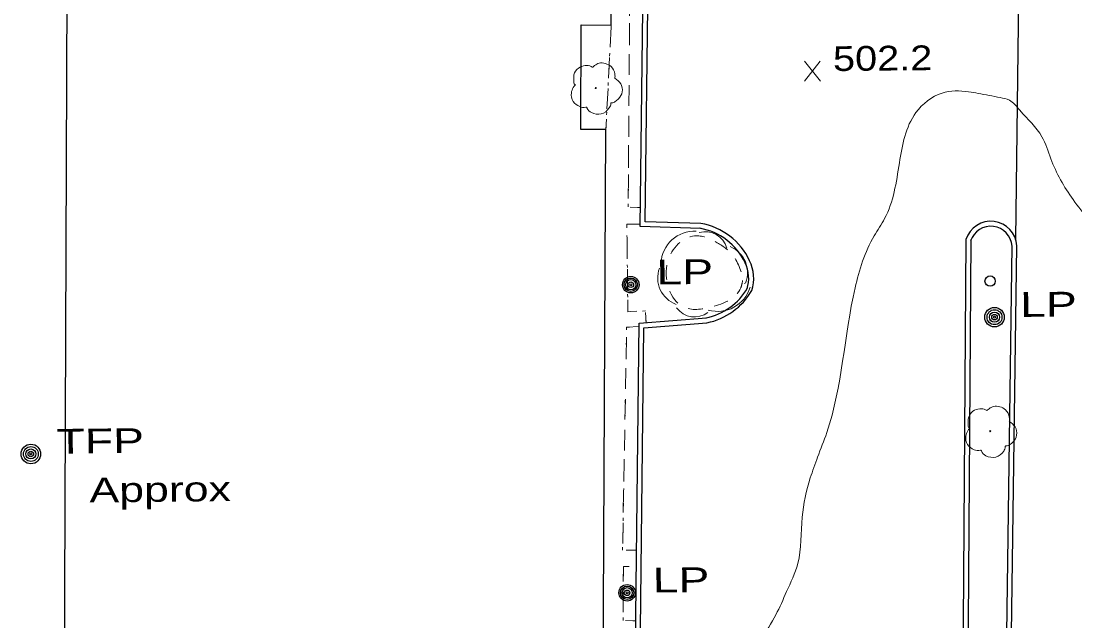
# Model space of a CAD drawing. Extents: x 2362213 to 2366494, y 6968794 to 6978110.
# Drawn here: x 2364038.5 to 2364243, y 6974850.3 to 6974966.6 of the extents above; entities that cross this region are included whole.
import ezdxf

# ---------------------------------------------------------------- set-up
doc = ezdxf.new("R2010")
doc.units = 0
doc.header["$LTSCALE"] = 1.9
doc.linetypes.add('DOTTED', pattern=[1.5, 0.3, -1.2])
doc.linetypes.add('SHORT_DASHED', pattern=[2.7, 1.5, -1.2])
for name, color, linetype, lineweight in [('11', 7, 'Continuous', 25), ('13', 7, 'Continuous', 13), ('2', 7, 'Continuous', 25), ('20', 7, 'Continuous', 25), ('29', 7, 'Continuous', 13), ('31', 7, 'Continuous', 25), ('35', 7, 'Continuous', 13)]:
    doc.layers.add(name, color=color, linetype=linetype, lineweight=lineweight)

msp = doc.modelspace()

# ---------------------------------------------------------------- linework, layer by layer
at = {"layer": '11'}
msp.add_lwpolyline([(2364144.499, 6974705.543), (2364144.65, 6974735.807), (2364151.03, 6974735.778), (2364151.301, 6974795.572), (2364145.771, 6974795.6), (2364145.92, 6974826.173), (2364151.409, 6974826.146), (2364152.012, 6974945.557), (2364147.142, 6974945.58), (2364147.239, 6974965.852), (2364153.059, 6974965.828), (2364153.569, 6975085.578), (2364148.939, 6975085.594), (2364149.041, 6975115.776), (2364154.952, 6975115.753), (2364155.191, 6975175.679), (2364150.001, 6975175.699), (2364150.119, 6975205.342), (2364048.33, 6975205.742), (2364046.369, 6974705.929)], close=True, dxfattribs=at)
at = {"layer": '13', "linetype": 'DOTTED'}
msp.add_line((2364152.012, 6974945.557), (2364153.029, 6974965.827), dxfattribs=at)
at = {"layer": '13'}
for p, q in [((2364152.82, 6974961.545), (2364153.012, 6974965.537)), ((2364156.564, 6974962.181), (2364156.596, 6974966.181)), ((2364152.517, 6974955.552), (2364152.719, 6974959.544)), ((2364156.521, 6974956.18), (2364156.553, 6974960.181)), ((2364152.214, 6974949.559), (2364152.416, 6974953.55)), ((2364156.479, 6974950.18), (2364156.51, 6974954.179)), ((2364152.012, 6974945.557), (2364152.113, 6974947.558)), ((2364156.436, 6974944.179), (2364156.468, 6974948.179)), ((2364156.393, 6974938.178), (2364156.425, 6974942.179)), ((2364156.35, 6974932.177), (2364156.382, 6974936.178)), ((2364158.727, 6974930.449), (2364156.726, 6974930.55)), ((2364156.161, 6974920.515), (2364156.113, 6974924.515)), ((2364156.228, 6974914.516), (2364156.18, 6974918.515)), ((2364159.789, 6974908.118), (2364159.72, 6974910.119)), ((2364156.108, 6974907.233), (2364158.426, 6974907.385)), ((2364155.924, 6974901.312), (2364155.996, 6974905.313)), ((2364155.811, 6974895.311), (2364155.883, 6974899.312)), ((2364155.708, 6974889.309), (2364155.78, 6974893.31)), ((2364155.595, 6974883.307), (2364155.667, 6974887.308)), ((2364155.492, 6974877.307), (2364155.564, 6974881.308)), ((2364155.38, 6974871.306), (2364155.451, 6974875.306)), ((2364155.277, 6974865.303), (2364155.349, 6974869.305)), ((2364157.939, 6974863.989), (2364155.939, 6974863.99)), ((2364155.354, 6974851.944), (2364155.376, 6974855.945)), ((2364157.79, 6974850.298), (2364155.789, 6974850.368))]:
    msp.add_line(p, q, dxfattribs=at)
at = {"layer": '13', "linetype": 'DOTTED'}
for points in [[(2364158.727, 6974930.449), (2364156.335, 6974930.566), (2364156.758, 6974987.024), (2364159.397, 6974987.069)], [(2364159.789, 6974908.118), (2364159.708, 6974910.399), (2364156.269, 6974910.236), (2364156.077, 6974927.215), (2364158.687, 6974927.22)], [(2364157.939, 6974863.989), (2364155.249, 6974863.993), (2364156.028, 6974907.232), (2364158.426, 6974907.385)], [(2364157.79, 6974850.298), (2364155.349, 6974850.384), (2364155.409, 6974860.824), (2364157.9, 6974860.778)]]:
    msp.add_lwpolyline(points, dxfattribs=at)
at = {"layer": '13'}
for points in [[(2364156.084, 6974926.515), (2364156.077, 6974927.215), (2364158.687, 6974927.22)], [(2364157.988, 6974910.322), (2364156.269, 6974910.236), (2364156.247, 6974912.516)], [(2364155.387, 6974857.945), (2364155.409, 6974860.824), (2364156.53, 6974860.805)]]:
    msp.add_lwpolyline(points, dxfattribs=at)
at = {"layer": '2'}
msp.add_line((2364231.509, 6974924.323), (2364232.2, 6974978.832), dxfattribs=at)
for points in [[(2364170.386, 6974926.411), (2364158.682, 6974926.739), (2364159.801, 6975021.385), (2364161.9, 6975204.204), (2364150.098, 6975204.381)], [(2364170.416, 6974927.371), (2364159.653, 6974927.669), (2364160.761, 6975021.375), (2364162.871, 6975205.153), (2364150.109, 6975205.341)], [(2364221.858, 6974924.261), (2364221.316, 6974849.932), (2364219.62, 6974747.611)], [(2364222.818, 6974924.25), (2364222.276, 6974849.922), (2364220.581, 6974747.59)], [(2364228.65, 6974747.647), (2364229.767, 6974847.793), (2364230.8, 6974923.046)], [(2364229.611, 6974747.636), (2364230.727, 6974847.782), (2364231.761, 6974923.035)], [(2364156.663, 6974749.151), (2364158.43, 6974908.005), (2364171.521, 6974909.05)], [(2364157.623, 6974749.14), (2364159.379, 6974907.114), (2364171.6, 6974908.091)]]:
    msp.add_lwpolyline(points, dxfattribs=at)
for centre, radius, start, end in [((2364168.111, 6974914.536), 12.08, 25.45495, 79.81805), ((2364168.111, 6974914.536), 13.04, 25.45495, 79.81805), ((2364226.693, 6974922.705), 5.079, 3.72178, 162.16418), ((2364226.693, 6974922.705), 4.119, 3.72178, 162.16418), ((2364172.998, 6974916.734), 7.684, 342.11796, 26.31952), ((2364172.998, 6974916.734), 6.724, 342.11796, 26.31952), ((2364169.016, 6974920.852), 12.06, 281.44766, 330.16517), ((2364169.016, 6974920.852), 13.02, 281.44766, 330.16517)]:
    msp.add_arc(centre, radius, start, end, dxfattribs=at)
at = {"layer": '20'}
for centre, radius in [((2364156.839, 6974915.481), 1.6), ((2364156.839, 6974915.481), 1.3), ((2364156.839, 6974915.481), 1), ((2364156.839, 6974915.481), 0.539), ((2364226.556, 6974916.185), 1), ((2364156.839, 6974915.481), 0.192), ((2364227.402, 6974909.183), 1.9), ((2364227.402, 6974909.183), 1.442), ((2364227.402, 6974909.183), 0.973), ((2364227.402, 6974909.183), 0.539), ((2364227.402, 6974909.183), 0.192), ((2364040.446, 6974882.651), 1.9), ((2364040.446, 6974882.651), 1.442), ((2364040.446, 6974882.651), 0.973), ((2364040.446, 6974882.651), 0.539), ((2364040.446, 6974882.651), 0.192), ((2364156.118, 6974855.732), 1.6), ((2364156.118, 6974855.732), 1.3), ((2364156.118, 6974855.732), 1), ((2364156.118, 6974855.732), 0.539), ((2364156.118, 6974855.732), 0.192)]:
    msp.add_circle(centre, radius, dxfattribs=at)
at = {"layer": '29'}
for centre in [(2364150.036, 6974953.628), (2364226.563, 6974887.074)]:
    msp.add_circle(centre, 0.1, dxfattribs=at)
for centre, radius, start, end in [((2364169.223, 6974919.358), 6.525, 87.4639, 177.4639), ((2364171.285, 6974921.427), 4.347, 15.47608, 105.47608), ((2364174.064, 6974917.827), 5.44, 338.17694, 68.17694), ((2364167.506, 6974916.768), 5.44, 159.6241, 249.6241), ((2364173.718, 6974916.83), 6.525, 253.61946, 343.61946), ((2364169.217, 6974913.573), 4.347, 216.6818, 306.6818)]:
    msp.add_arc(centre, radius, start, end, dxfattribs=at)
for points in [[(2364146.07, 6974954.2), (2364146.09, 6974954.21), (2364146.009, 6974954.279), (2364145.773, 6974954.908), (2364145.811, 6974956.188), (2364146.699, 6974957.487), (2364148.004, 6974957.969), (2364149.126, 6974957.78), (2364149.357, 6974957.652), (2364149.427, 6974957.653), (2364149.477, 6974957.693), (2364149.824, 6974957.987), (2364150.69, 6974958.435), (2364151.9, 6974958.366), (2364153.016, 6974957.777), (2364153.75, 6974956.354), (2364153.758, 6974955.494)], [(2364153.748, 6974955.514), (2364154.888, 6974954.455), (2364155.173, 6974952.866), (2364154.466, 6974951.54), (2364153.811, 6974950.994), (2364153.143, 6974950.778), (2364152.993, 6974950.766), (2364152.974, 6974950.656), (2364152.652, 6974949.753), (2364151.113, 6974948.588), (2364149.221, 6974948.87), (2364148.322, 6974949.812), (2364148.25, 6974949.941), (2364148.131, 6974949.92), (2364146.919, 6974950.039), (2364145.65, 6974951.036), (2364145.304, 6974952.672), (2364145.675, 6974953.696), (2364146, 6974954.139), (2364146.07, 6974954.19)], [(2364222.597, 6974887.645), (2364222.617, 6974887.656), (2364222.536, 6974887.725), (2364222.3, 6974888.354), (2364222.338, 6974889.634), (2364223.226, 6974890.932), (2364224.531, 6974891.415), (2364225.653, 6974891.226), (2364225.884, 6974891.098), (2364225.954, 6974891.098), (2364226.004, 6974891.139), (2364226.351, 6974891.432), (2364227.217, 6974891.881), (2364228.428, 6974891.812), (2364229.543, 6974891.223), (2364230.277, 6974889.8), (2364230.285, 6974888.94)], [(2364230.275, 6974888.96), (2364231.415, 6974887.899), (2364231.701, 6974886.312), (2364230.993, 6974884.985), (2364230.338, 6974884.439), (2364229.67, 6974884.223), (2364229.52, 6974884.211), (2364229.501, 6974884.101), (2364229.18, 6974883.198), (2364227.641, 6974882.034), (2364225.748, 6974882.316), (2364224.849, 6974883.257), (2364224.778, 6974883.386), (2364224.658, 6974883.365), (2364223.447, 6974883.483), (2364222.177, 6974884.481), (2364221.832, 6974886.118), (2364222.202, 6974887.142), (2364222.528, 6974887.585), (2364222.597, 6974887.635)]]:
    msp.add_spline(points, degree=3, dxfattribs=at)
at = {"layer": '29', "linetype": 'SHORT_DASHED'}
msp.add_spline([(2364178.532, 6974916.298), (2364178.166, 6974914.854), (2364172.531, 6974911.161), (2364167.062, 6974911.159), (2364164.016, 6974920), (2364169.219, 6974924.96), (2364173.381, 6974923.759), (2364176.605, 6974921.2), (2364178.898, 6974915.711)], degree=3, dxfattribs=at)
at = {"layer": '31', "lineweight": 13}
for p, q in [((2364193.645, 6974954.954), (2364190.529, 6974958.804)), ((2364190.566, 6974954.924), (2364193.608, 6974958.834))]:
    msp.add_line(p, q, dxfattribs=at)
at = {"layer": '35'}
msp.add_spline([(2364272.528, 6974950.795), (2364271.344, 6974949.133), (2364269.528, 6974946.526), (2364268.177, 6974942.503), (2364266.551, 6974935.757), (2364264.265, 6974930.034), (2364262.423, 6974927.077), (2364260.748, 6974923.531), (2364257.996, 6974921.615), (2364254.304, 6974920.74), (2364250.977, 6974921.418), (2364248.697, 6974923.496), (2364245.644, 6974927.978), (2364242.636, 6974932.008), (2364238.33, 6974939.919), (2364236.61, 6974944.172), (2364232.311, 6974949.302), (2364230.281, 6974951.282), (2364228.527, 6974951.776), (2364224.209, 6974952.585), (2364222.386, 6974952.896), (2364217.238, 6974952.638), (2364212.165, 6974948.86), (2364208.946, 6974939.099), (2364206.079, 6974928.301), (2364204.041, 6974924.951), (2364200.347, 6974914.856), (2364194.854, 6974886.791), (2364193.089, 6974882.055), (2364191.668, 6974878.001), (2364190.081, 6974870.386), (2364189.236, 6974861.406), (2364187.067, 6974855.957), (2364184.97, 6974851.456), (2364182.295, 6974846.691), (2364180.887, 6974843.336), (2364178.238, 6974837.941), (2364174.389, 6974827.385), (2364171.929, 6974808.39), (2364168.108, 6974789.712), (2364161.255, 6974748.895)], degree=3, dxfattribs=at)

# ---------------------------------------------------------------- texts
at = {"layer": '20'}
for s, width, p in [('  LP', 1.4, (2364156.839, 6974915.481)), ('  LP', 1.4, (2364227.402, 6974909.182)), ('  TFP', 1.4, (2364040.446, 6974882.651)), ('Approx', 1.35, (2364051.816, 6974873.249)), ('  LP', 1.4, (2364156.118, 6974855.732))]:
    msp.add_text(s, height=4.8, rotation=0.546, dxfattribs=dict(at, width=width)).set_placement(p)
at = {"layer": '31', "width": 1.2}
msp.add_text('502.2', height=4.8, rotation=0.546, dxfattribs=at).set_placement((2364196.086, 6974956.917))

doc.saveas('drawing.dxf')
